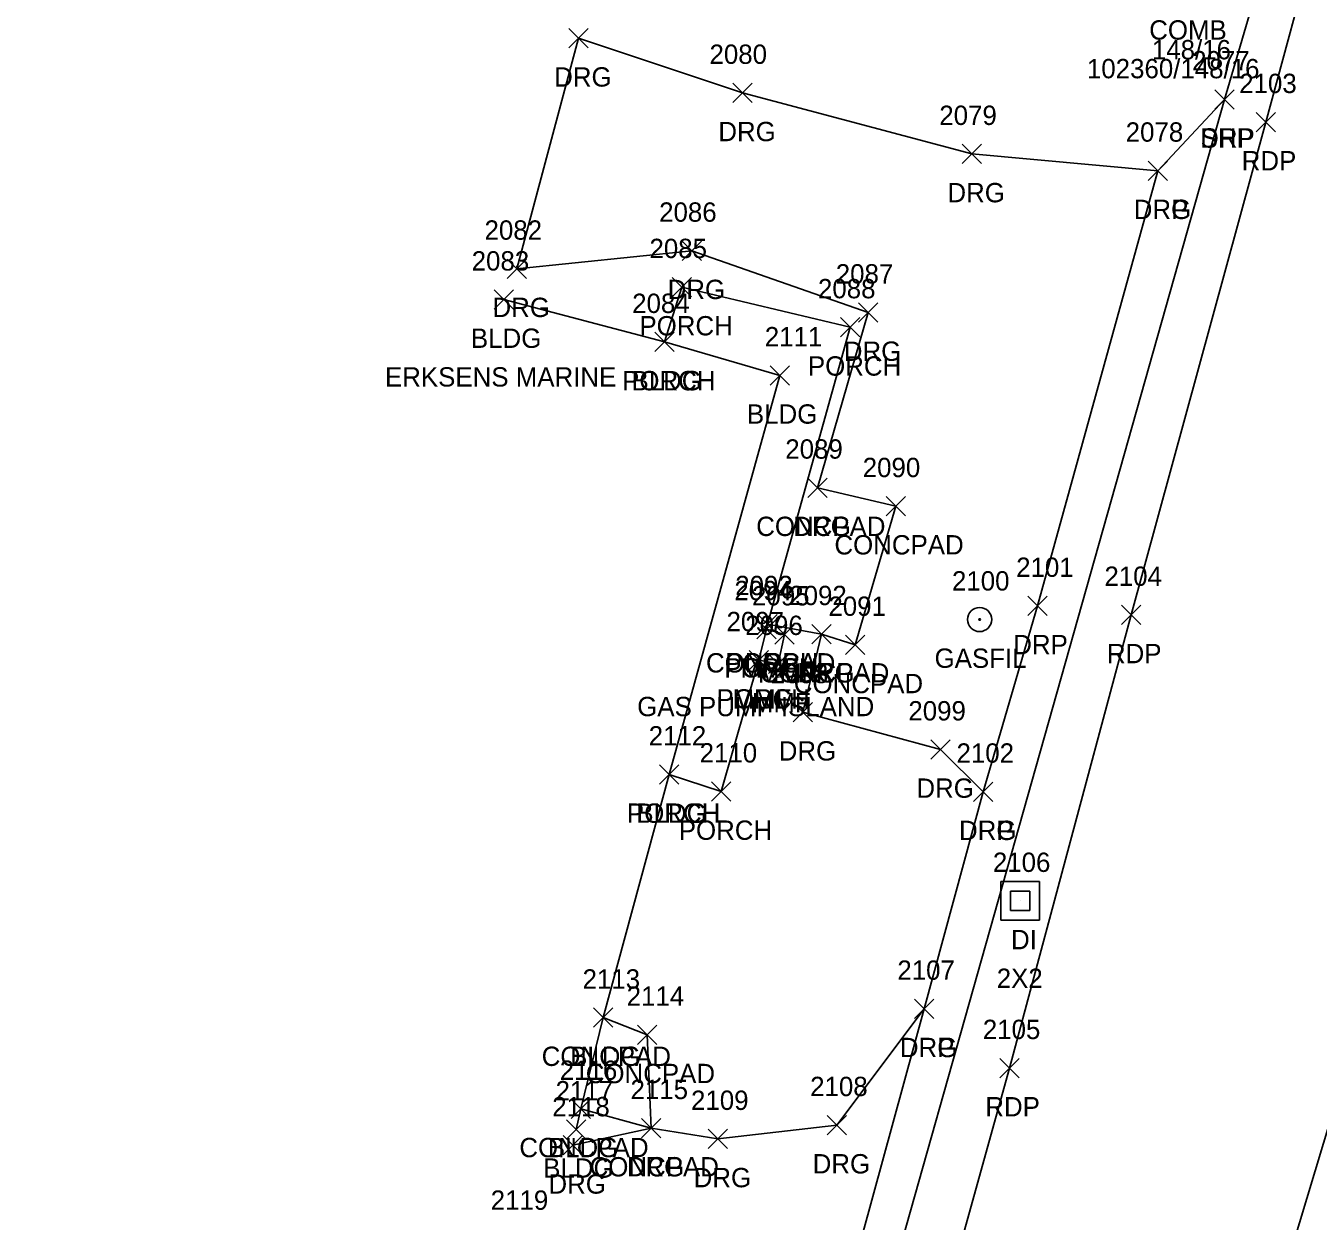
# Model space of a CAD drawing. Extents: x 1443071 to 1445292, y 614024 to 622563.
# Drawn here: x 1444521.8 to 1444655.5, y 622193 to 622316.6 of the extents above; entities that cross this region are included whole.
import ezdxf

# ---------------------------------------------------------------- set-up
doc = ezdxf.new("R2010")
doc.units = 0
for name, color, linetype in [('D_A', 7, 'Continuous'), ('D_C', 7, 'Continuous'), ('D_I', 7, 'Continuous'), ('DS', 7, 'Continuous'), ('L_A', 7, 'Continuous'), ('L_C', 7, 'Continuous'), ('L_I', 7, 'Continuous'), ('L_TIC', 7, 'Continuous'), ('LBC', 7, 'Continuous'), ('LBF', 7, 'Continuous'), ('LDEFAULT', 7, 'Continuous'), ('LS', 7, 'Continuous'), ('P_A', 7, 'Continuous'), ('P_I', 7, 'Continuous'), ('P_TIC', 7, 'Continuous'), ('PET', 7, 'Continuous'), ('PSP', 7, 'Continuous'), ('R_A', 7, 'Continuous'), ('R_I', 7, 'Continuous'), ('R_TIC', 7, 'Continuous'), ('RDG', 7, 'Continuous'), ('RDP', 7, 'Continuous'), ('U_A', 7, 'Continuous'), ('U_C', 7, 'Continuous'), ('U_I', 7, 'Continuous'), ('UMFC', 7, 'Continuous')]:
    doc.layers.add(name, color=color, linetype=linetype)

msp = doc.modelspace()

# ---------------------------------------------------------------- linework, layer by layer
at = {"layer": 'DS'}
for p, q in [((1444622.64, 622228.09), (1444626.64, 622228.09)), ((1444622.64, 622224.09), (1444622.64, 622228.09)), ((1444626.64, 622228.09), (1444626.64, 622224.09)), ((1444623.64, 622225.09), (1444623.64, 622227.09)), ((1444623.64, 622227.09), (1444625.64, 622227.09)), ((1444624.65, 622226.09), (1444624.65, 622226.09)), ((1444624.65, 622226.09), (1444624.65, 622226.09)), ((1444625.64, 622227.09), (1444625.64, 622225.09)), ((1444625.64, 622225.09), (1444623.64, 622225.09)), ((1444626.64, 622224.09), (1444622.64, 622224.09))]:
    msp.add_line(p, q, dxfattribs=at)
at = {"layer": 'L_TIC'}
for points in [[(1444588.63, 622288.59), (1444590.63, 622290.59)], [(1444590.63, 622288.59), (1444588.63, 622290.59)], [(1444570.24, 622287.3), (1444572.24, 622289.3)], [(1444572.24, 622287.3), (1444570.24, 622289.3)], [(1444606.07, 622284.43), (1444608.07, 622286.43)], [(1444608.07, 622284.43), (1444606.07, 622286.43)], [(1444586.85, 622282.91), (1444588.85, 622284.91)], [(1444588.85, 622282.91), (1444586.85, 622284.91)], [(1444586.85, 622282.91), (1444588.85, 622284.91)], [(1444588.85, 622282.91), (1444586.85, 622284.91)], [(1444598.79, 622279.46), (1444600.79, 622281.46)], [(1444600.79, 622279.46), (1444598.79, 622281.46)], [(1444602.69, 622267.84), (1444604.69, 622269.84)], [(1444604.69, 622267.84), (1444602.69, 622269.84)], [(1444610.78, 622265.93), (1444612.78, 622267.93)], [(1444612.78, 622265.93), (1444610.78, 622267.93)], [(1444597.42, 622253.2), (1444599.42, 622255.2)], [(1444599.42, 622253.2), (1444597.42, 622255.2)], [(1444597.42, 622253.2), (1444599.42, 622255.2)], [(1444599.42, 622253.2), (1444597.42, 622255.2)], [(1444597.5, 622253.72), (1444599.5, 622255.72)], [(1444599.5, 622253.72), (1444597.5, 622255.72)], [(1444597.5, 622253.72), (1444599.5, 622255.72)], [(1444599.5, 622253.72), (1444597.5, 622255.72)], [(1444599.25, 622252.66), (1444601.25, 622254.66)], [(1444601.25, 622252.66), (1444599.25, 622254.66)], [(1444603.1, 622252.69), (1444605.1, 622254.69)], [(1444605.1, 622252.69), (1444603.1, 622254.69)], [(1444606.58, 622251.58), (1444608.58, 622253.58)], [(1444608.58, 622251.58), (1444606.58, 622253.58)], [(1444596.61, 622249.99), (1444598.61, 622251.99)], [(1444598.61, 622249.99), (1444596.61, 622251.99)], [(1444596.61, 622249.99), (1444598.61, 622251.99)], [(1444598.61, 622249.99), (1444596.61, 622251.99)], [(1444598.6, 622249.6), (1444600.6, 622251.6)], [(1444600.6, 622249.6), (1444598.6, 622251.6)], [(1444587.35, 622238.17), (1444589.35, 622240.17)], [(1444589.35, 622238.17), (1444587.35, 622240.17)], [(1444587.35, 622238.17), (1444589.35, 622240.17)], [(1444589.35, 622238.17), (1444587.35, 622240.17)], [(1444592.7, 622236.41), (1444594.7, 622238.41)], [(1444594.7, 622236.41), (1444592.7, 622238.41)], [(1444580.5, 622213.02), (1444582.5, 622215.02)], [(1444582.5, 622213.02), (1444580.5, 622215.02)], [(1444580.5, 622213.02), (1444582.5, 622215.02)], [(1444582.5, 622213.02), (1444580.5, 622215.02)], [(1444585.06, 622211.24), (1444587.06, 622213.24)], [(1444587.06, 622211.24), (1444585.06, 622213.24)], [(1444578.2, 622203.58), (1444580.2, 622205.58)], [(1444580.2, 622203.58), (1444578.2, 622205.58)], [(1444578.2, 622203.58), (1444580.2, 622205.58)], [(1444580.2, 622203.58), (1444578.2, 622205.58)], [(1444577.72, 622201.46), (1444579.72, 622203.46)], [(1444579.72, 622201.46), (1444577.72, 622203.46)], [(1444585.47, 622201.59), (1444587.47, 622203.59)], [(1444587.47, 622201.59), (1444585.47, 622203.59)]]:
    msp.add_lwpolyline(points, dxfattribs=at)
at = {"layer": 'LBC'}
msp.add_lwpolyline([(1444571.24, 622288.3), (1444587.85, 622283.91), (1444599.79, 622280.46), (1444588.35, 622239.17), (1444581.5, 622214.02), (1444579.2, 622204.58), (1444578.72, 622202.46)], dxfattribs=at)
at = {"layer": 'LBF'}
msp.add_lwpolyline([(1444587.85, 622283.91), (1444589.63, 622289.59), (1444607.07, 622285.43), (1444598.5, 622254.72), (1444598.42, 622254.2), (1444597.61, 622250.99), (1444593.7, 622237.41), (1444588.35, 622239.17)], dxfattribs=at)
at = {"layer": 'LDEFAULT'}
msp.add_lwpolyline([(1444598.42, 622254.2), (1444600.25, 622253.66), (1444599.6, 622250.6), (1444597.61, 622250.99)], dxfattribs=at)
at = {"layer": 'LS'}
for points in [[(1444603.69, 622268.84), (1444611.78, 622266.93), (1444607.58, 622252.58), (1444604.1, 622253.69), (1444598.5, 622254.72)], [(1444581.5, 622214.02), (1444586.06, 622212.24), (1444586.47, 622202.59), (1444579.2, 622204.58)]]:
    msp.add_lwpolyline(points, dxfattribs=at)
at = {"layer": 'P_TIC'}
for points in [[(1444644.77, 622308.01), (1444646.77, 622310.01)], [(1444646.77, 622308.01), (1444644.77, 622310.01)], [(1444649.07, 622305.66), (1444651.07, 622307.66)], [(1444651.07, 622305.66), (1444649.07, 622307.66)], [(1444635.13, 622254.68), (1444637.13, 622256.68)], [(1444637.13, 622254.68), (1444635.13, 622256.68)], [(1444622.55, 622207.8), (1444624.55, 622209.8)], [(1444624.55, 622207.8), (1444622.55, 622209.8)]]:
    msp.add_lwpolyline(points, dxfattribs=at)
at = {"layer": 'PET'}
for points in [[(1444754.44, 622544.13), (1444741.07, 622497.37), (1444724.21, 622436.63), (1444710.62, 622388.87), (1444697.45, 622342.15), (1444675, 622264.13), (1444650.85, 622183.92), (1444630.28, 622116), (1444610.88, 622049.25), (1444594.96, 621996.24), (1444563.37, 621884.27), (1444533.4, 621779.05), (1444495.09, 621640.86), (1444437.04, 621433.18), (1444409.83, 621332.84), (1444393.99, 621275.61), (1444360.23, 621155.32)], [(1444707.59, 622509.11), (1444700.19, 622484.07), (1444679.05, 622409.28), (1444655.77, 622327.83), (1444650.07, 622306.66), (1444636.13, 622255.68), (1444623.55, 622208.8), (1444606.26, 622146.53), (1444595.29, 622106.04), (1444582.56, 622060.23), (1444534.43, 621893.79), (1444481.57, 621704.27), (1444439.29, 621553.82), (1444408.11, 621445.28), (1444395.03, 621397.39), (1444367.96, 621301.44), (1444350.41, 621238.76), (1444319.14, 621126.97)]]:
    msp.add_lwpolyline(points, dxfattribs=at)
at = {"layer": 'PSP'}
msp.add_lwpolyline([(1444703.05, 622509.58), (1444696.35, 622485.04), (1444679.96, 622426.95), (1444670.67, 622398.4), (1444651.65, 622328.99), (1444645.77, 622309.01), (1444600.31, 622147.99), (1444589.19, 622108.06), (1444575.49, 622063.15), (1444529.28, 621895.39), (1444476.53, 621706.36), (1444455.46, 621630.82), (1444442.09, 621578.45), (1444424.77, 621519.75), (1444412.09, 621475.26), (1444390.88, 621397.93), (1444363.76, 621301.82), (1444345.99, 621239.2), (1444324.65, 621163.68)], dxfattribs=at)
at = {"layer": 'R_TIC'}
for points in [[(1444577.96, 622314.33), (1444579.96, 622316.33)], [(1444579.96, 622314.33), (1444577.96, 622316.33)], [(1444594.93, 622308.68), (1444596.93, 622310.68)], [(1444596.93, 622308.68), (1444594.93, 622310.68)], [(1444644.77, 622308.01), (1444646.77, 622310.01)], [(1444646.77, 622308.01), (1444644.77, 622310.01)], [(1444618.63, 622302.36), (1444620.63, 622304.36)], [(1444620.63, 622302.36), (1444618.63, 622304.36)], [(1444637.9, 622300.63), (1444639.9, 622302.63)], [(1444639.9, 622300.63), (1444637.9, 622302.63)], [(1444637.9, 622300.63), (1444639.9, 622302.63)], [(1444639.9, 622300.63), (1444637.9, 622302.63)], [(1444589.69, 622292.35), (1444591.69, 622294.35)], [(1444591.69, 622292.35), (1444589.69, 622294.35)], [(1444571.57, 622290.49), (1444573.57, 622292.49)], [(1444573.57, 622290.49), (1444571.57, 622292.49)], [(1444607.91, 622285.96), (1444609.91, 622287.96)], [(1444609.91, 622285.96), (1444607.91, 622287.96)], [(1444602.69, 622267.84), (1444604.69, 622269.84)], [(1444604.69, 622267.84), (1444602.69, 622269.84)], [(1444625.44, 622255.61), (1444627.44, 622257.61)], [(1444627.44, 622255.61), (1444625.44, 622257.61)], [(1444603.1, 622252.69), (1444605.1, 622254.69)], [(1444605.1, 622252.69), (1444603.1, 622254.69)], [(1444601.18, 622244.61), (1444603.18, 622246.61)], [(1444603.18, 622244.61), (1444601.18, 622246.61)], [(1444615.42, 622240.76), (1444617.42, 622242.76)], [(1444617.42, 622240.76), (1444615.42, 622242.76)], [(1444619.83, 622236.39), (1444621.83, 622238.39)], [(1444621.83, 622236.39), (1444619.83, 622238.39)], [(1444619.83, 622236.39), (1444621.83, 622238.39)], [(1444621.83, 622236.39), (1444619.83, 622238.39)], [(1444613.71, 622213.93), (1444615.71, 622215.93)], [(1444615.71, 622213.93), (1444613.71, 622215.93)], [(1444613.71, 622213.93), (1444615.71, 622215.93)], [(1444615.71, 622213.93), (1444613.71, 622215.93)], [(1444585.47, 622201.59), (1444587.47, 622203.59)], [(1444587.47, 622201.59), (1444585.47, 622203.59)], [(1444604.69, 622201.9), (1444606.69, 622203.9)], [(1444606.69, 622201.9), (1444604.69, 622203.9)], [(1444577.36, 622199.81), (1444579.36, 622201.81)], [(1444579.36, 622199.81), (1444577.36, 622201.81)], [(1444592.38, 622200.47), (1444594.38, 622202.47)], [(1444594.38, 622200.47), (1444592.38, 622202.47)]]:
    msp.add_lwpolyline(points, dxfattribs=at)
at = {"layer": 'RDG'}
for points in [[(1444638.9, 622301.63), (1444619.63, 622303.36), (1444595.93, 622309.68), (1444578.96, 622315.33), (1444572.57, 622291.49), (1444590.69, 622293.35), (1444608.91, 622286.96), (1444603.69, 622268.84)], [(1444604.1, 622253.69), (1444602.18, 622245.61), (1444616.42, 622241.76), (1444620.83, 622237.39)], [(1444614.71, 622214.93), (1444605.69, 622202.9), (1444593.38, 622201.47), (1444586.47, 622202.59), (1444578.36, 622200.81)]]:
    msp.add_lwpolyline(points, dxfattribs=at)
at = {"layer": 'RDP'}
msp.add_lwpolyline([(1444645.77, 622309.01), (1444638.9, 622301.63), (1444626.44, 622256.61), (1444620.83, 622237.39), (1444614.71, 622214.93), (1444596.67, 622148.99), (1444585.03, 622109.27), (1444575.08, 622074.59), (1444575.49, 622063.15)], dxfattribs=at)
at = {"layer": 'UMFC'}
msp.add_line((1444620.45, 622255.2), (1444620.45, 622255.2), dxfattribs=at)
for radius in [1.25, 0.0833]:
    msp.add_circle((1444620.45, 622255.2), radius, dxfattribs=at)

# ---------------------------------------------------------------- texts
at = {"layer": 'D_A'}
msp.add_text('DI', height=2, dxfattribs=at).set_placement((1444623.7, 622221.09))
at = {"layer": 'D_C'}
msp.add_text('2X2', height=2, dxfattribs=at).set_placement((1444622.22, 622217.09))
at = {"layer": 'D_I'}
msp.add_text('2106', height=2, dxfattribs=at).set_placement((1444621.82, 622229.09))
at = {"layer": 'L_A'}
for s, p in [('PORCH', (1444585.26, 622284.59)), ('BLDG', (1444567.83, 622283.3)), ('PORCH', (1444602.69, 622280.43)), ('PORCH', (1444583.47, 622278.91)), ('BLDG', (1444584.44, 622278.91)), ('BLDG', (1444596.38, 622275.46)), ('CONCPAD', (1444597.34, 622263.84)), ('CONCPAD', (1444605.43, 622261.93)), ('CONCPAD', (1444592.15, 622249.72)), ('PORCH', (1444594.04, 622249.2)), ('PORCH', (1444594.13, 622249.72)), ('MMF', (1444595.71, 622249.2)), ('MMF', (1444597.53, 622248.66)), ('CONCPAD', (1444597.74, 622248.69)), ('CONCPAD', (1444601.23, 622247.58)), ('PORCH', (1444593.24, 622245.99)), ('MMF', (1444594.9, 622245.99)), ('MMF', (1444596.89, 622245.6)), ('PORCH', (1444583.97, 622234.17)), ('BLDG', (1444584.94, 622234.17)), ('PORCH', (1444589.33, 622232.41)), ('CONCPAD', (1444575.15, 622209.02)), ('BLDG', (1444578.09, 622209.02)), ('CONCPAD', (1444579.71, 622207.24)), ('CONCPAD', (1444572.84, 622199.58)), ('BLDG', (1444575.79, 622199.58)), ('BLDG', (1444575.31, 622197.46)), ('CONCPAD', (1444580.11, 622197.59))]:
    msp.add_text(s, height=2, dxfattribs=at).set_placement(p)
at = {"layer": 'L_C'}
for s, p in [('ERKSENS MARINE', (1444558.94, 622279.3)), ('GAS PUMP ISLAND', (1444585.03, 622245.2))]:
    msp.add_text(s, height=2, dxfattribs=at).set_placement(p)
at = {"layer": 'L_I'}
for s, p in [('2085', (1444586.3, 622292.59)), ('2083', (1444567.91, 622291.3)), ('2088', (1444603.73, 622288.43)), ('2084', (1444584.51, 622286.91)), ('2084', (1444584.51, 622286.91)), ('2111', (1444598.23, 622283.46)), ('2089', (1444600.35, 622271.84)), ('2090', (1444608.36, 622269.93)), ('2094', (1444595.08, 622257.2)), ('2094', (1444595.08, 622257.2)), ('2093', (1444595.17, 622257.72)), ('2093', (1444595.17, 622257.72)), ('2095', (1444596.91, 622256.66)), ('2092', (1444600.76, 622256.69)), ('2091', (1444604.81, 622255.58)), ('2097', (1444594.27, 622253.99)), ('2097', (1444594.27, 622253.99)), ('2096', (1444596.21, 622253.6)), ('2112', (1444586.22, 622242.17)), ('2112', (1444586.22, 622242.17)), ('2110', (1444591.49, 622240.41)), ('2113', (1444579.38, 622217.02)), ('2113', (1444579.38, 622217.02)), ('2114', (1444583.94, 622215.24)), ('2116', (1444577.02, 622207.58)), ('2116', (1444577.02, 622207.58)), ('2117', (1444576.59, 622205.46)), ('2115', (1444584.34, 622205.59))]:
    msp.add_text(s, height=2, dxfattribs=at).set_placement(p)
at = {"layer": 'P_A'}
for s, p in [('SHP', (1444643.31, 622304.01)), ('RDP', (1444647.56, 622301.66)), ('RDP', (1444633.62, 622250.68)), ('RDP', (1444621.04, 622203.8))]:
    msp.add_text(s, height=2, dxfattribs=at).set_placement(p)
at = {"layer": 'P_I'}
for s, p in [('2077', (1444642.43, 622312.01)), ('2103', (1444647.3, 622309.66)), ('2104', (1444633.36, 622258.68)), ('2105', (1444620.78, 622211.8))]:
    msp.add_text(s, height=2, dxfattribs=at).set_placement(p)
at = {"layer": 'R_A'}
for s, p in [('DRG', (1444576.44, 622310.33)), ('DRG', (1444593.42, 622304.68)), ('DRP', (1444643.26, 622304.01)), ('DRG', (1444617.12, 622298.36)), ('DRG', (1444636.39, 622296.63)), ('DRP', (1444636.39, 622296.63)), ('DRG', (1444588.18, 622288.35)), ('DRG', (1444570.06, 622286.49)), ('DRG', (1444606.4, 622281.96)), ('DRG', (1444601.18, 622263.84)), ('DRP', (1444623.93, 622251.61)), ('DRG', (1444601.58, 622248.69)), ('DRG', (1444599.67, 622240.61)), ('DRG', (1444613.91, 622236.76)), ('DRG', (1444618.32, 622232.39)), ('DRP', (1444618.32, 622232.39)), ('DRG', (1444612.2, 622209.93)), ('DRP', (1444612.2, 622209.93)), ('DRG', (1444583.95, 622197.59)), ('DRG', (1444603.18, 622197.9)), ('DRG', (1444575.85, 622195.81)), ('DRG', (1444590.87, 622196.47))]:
    msp.add_text(s, height=2, dxfattribs=at).set_placement(p)
at = {"layer": 'R_I'}
for s, p in [('2080', (1444592.51, 622312.68)), ('2077', (1444642.43, 622312.01)), ('2079', (1444616.28, 622306.36)), ('2078', (1444635.56, 622304.63)), ('2078', (1444635.56, 622304.63)), ('2086', (1444587.3, 622296.35)), ('2082', (1444569.24, 622294.49)), ('2087', (1444605.57, 622289.96)), ('2089', (1444600.35, 622271.84)), ('2101', (1444624.23, 622259.61)), ('2092', (1444600.76, 622256.69)), ('2098', (1444598.84, 622248.61)), ('2099', (1444613.08, 622244.76)), ('2102', (1444618.06, 622240.39)), ('2102', (1444618.06, 622240.39)), ('2107', (1444611.94, 622217.93)), ('2107', (1444611.94, 622217.93)), ('2115', (1444584.34, 622205.59)), ('2108', (1444602.92, 622205.9)), ('2118', (1444576.24, 622203.81)), ('2109', (1444590.6, 622204.47)), ('2119', (1444569.88, 622194.14))]:
    msp.add_text(s, height=2, dxfattribs=at).set_placement(p)
at = {"layer": 'U_A'}
for s, p in [('COMB', (1444637.99, 622315.19)), ('GASFIL', (1444615.79, 622250.2))]:
    msp.add_text(s, height=2, dxfattribs=at).set_placement(p)
at = {"layer": 'U_C'}
for s, p in [('148/16', (1444638.27, 622313.15)), ('102360/148/16', (1444631.55, 622311.19))]:
    msp.add_text(s, height=2, dxfattribs=at).set_placement(p)
at = {"layer": 'U_I'}
msp.add_text('2100', height=2, dxfattribs=at).set_placement((1444617.59, 622258.2))

doc.saveas('drawing.dxf')
